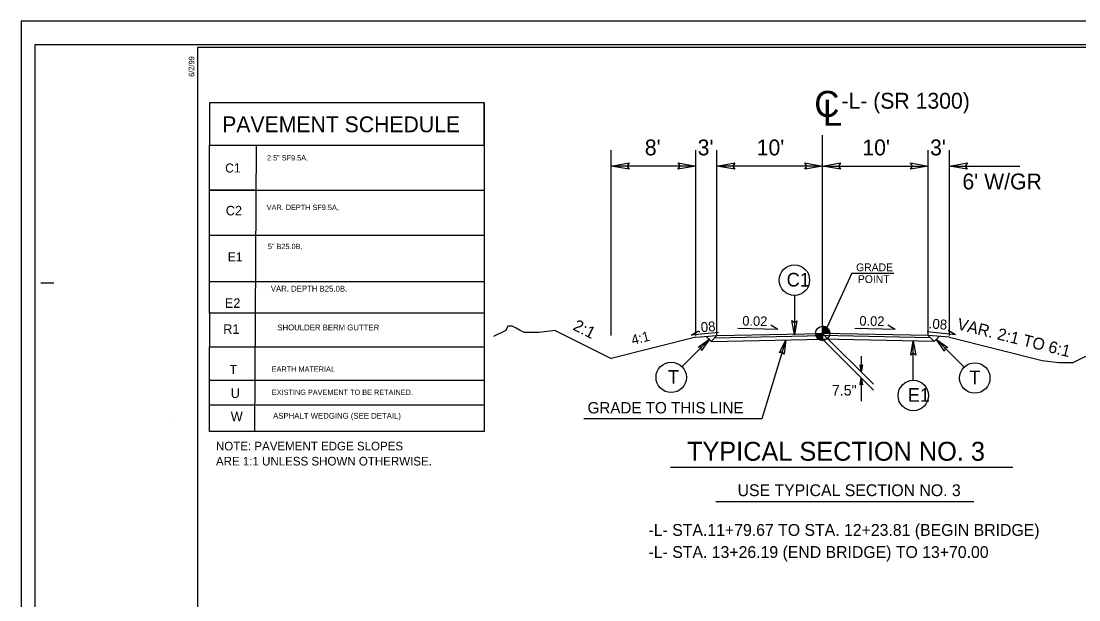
# Model space of a CAD drawing. Extents: x 1818040 to 1825768, y 638918 to 648046.
# Drawn here: x 1820431 to 1821432, y 644582 to 645130 of the extents above; entities that cross this region are included whole.
import ezdxf

# ---------------------------------------------------------------- set-up
doc = ezdxf.new("R2010")
doc.units = 0
for name, color, linetype in [('Old_Level_1', 7, 'Continuous'), ('Prop Dimension', 7, 'Continuous'), ('Prop Dimension Text', 7, 'Continuous'), ('Prop Pavement Schedule Description CELL', 7, 'Continuous'), ('Sheet Plot Border Inside CELL', 7, 'Continuous'), ('Sheet Plot Border Outside CELL', 7, 'Continuous'), ('Sheet Typical CELL', 7, 'Continuous'), ('Typical Grade Point Symbol CELL', 7, 'Continuous'), ('Typical ID Circle CELL', 7, 'Continuous'), ('Typical Pavement Slope CELL', 7, 'Continuous'), ('Typical Pavement Slope Information CELL', 7, 'Continuous'), ('Typical Shoulder Slope CELL', 7, 'Continuous'), ('Typical Slope Point Local CELL', 7, 'Continuous'), ('Typical Terminator CELL', 7, 'Continuous'), ('Typical Text Centerline CELL', 7, 'Continuous'), ('Typical Text General CELL', 7, 'Continuous'), ('Typical Text Grade Point CELL', 7, 'Continuous'), ('Typical Text ID Circle CELL', 7, 'Continuous'), ('Typical Text Label CELL', 7, 'Continuous')]:
    doc.layers.add(name, color=color, linetype=linetype)

msp = doc.modelspace()

# ---------------------------------------------------------------- linework, layer by layer
at = {"layer": 'Old_Level_1'}
for p, q in [((1820989.5, 644832.1), (1820989.5, 645007.5)), ((1821084, 644826.6), (1821079.3, 644831.2)), ((1821089.5, 644832.1), (1821084, 644826.6)), ((1821084, 644826.6), (1821189.5, 644828.7)), ((1821087.4, 644830), (1821189.5, 644832)), ((1821154.6, 644828), (1821131.9, 644753.4)), ((1821189.5, 644834.1), (1821237.5, 644786.1)), ((1821291.7, 644830), (1821189.5, 644832)), ((1821189.5, 644828.7), (1821237.7, 644780.5)), ((1821295.1, 644826.6), (1821189.5, 644828.7)), ((1821289.5, 644832.1), (1821295.1, 644826.6)), ((1821295.1, 644826.6), (1821299.8, 644831.2)), ((1821226, 644812.5), (1821226, 644797.7)), ((1821226, 644792.2), (1821226, 644769.9)), ((1821131.9, 644753.4), (1820963.4, 644753.4))]:
    msp.add_line(p, q, dxfattribs=at)
at = {"layer": 'Prop Dimension'}
for p, q in [((1821189.5, 644834.1), (1821189.5, 645021.8)), ((1821069.5, 644832.1), (1821069.5, 645007.5)), ((1821089.5, 644832.1), (1821089.5, 645007.5)), ((1821289.5, 644832.1), (1821289.5, 645007.5)), ((1821309.5, 644832.1), (1821309.5, 645007.5)), ((1821069.5, 644992.5), (1820989.5, 644992.5)), ((1821189.5, 644992.5), (1821089.5, 644992.5)), ((1821189.5, 644992.5), (1821289.5, 644992.5)), ((1821309.5, 644992.5), (1821376.1, 644992.5))]:
    msp.add_line(p, q, dxfattribs=at)
at = {"layer": 'Prop Pavement Schedule Description CELL'}
for p, q in [((1820869, 645052.4), (1820869, 645012.3)), ((1820653.3, 645012.3), (1820651.7, 644741.2)), ((1820869, 645012.3), (1820869, 644927.1)), ((1820869, 644938.9), (1820869, 644913.4)), ((1820609.3, 644927.1), (1820869, 644927.1)), ((1820609.3, 644883.3), (1820609.3, 644927.1)), ((1820869, 644913.4), (1820869, 644809)), ((1820609.3, 644853.2), (1820609.3, 644821.5)), ((1820869, 644809), (1820869, 644789.7)), ((1820609.3, 644789.7), (1820869, 644789.7)), ((1820869, 644789.7), (1820869, 644741.2)), ((1820574.6, 644754.4), (1820574.6, 644754.4))]:
    msp.add_line(p, q, dxfattribs=at)
msp.add_lwpolyline([(1820609.3, 645012.3), (1820869, 645012.3), (1820869, 645052.4), (1820609.3, 645052.4)], close=True, dxfattribs=at)
for points in [[(1820651.9, 644969.7), (1820609.3, 644969.7), (1820609.3, 645012.3), (1820869, 645012.3)], [(1820609.3, 644927.1), (1820609.3, 644969.7), (1820869, 644969.7)], [(1820869, 644853.2), (1820609.3, 644853.2), (1820609.3, 644883.3), (1820869, 644883.3)], [(1820609.3, 644757.4), (1820609.3, 644821.5), (1820869, 644821.5)], [(1820869, 644741.2), (1820609.3, 644741.2), (1820609.3, 644766.4), (1820869, 644766.4)]]:
    msp.add_lwpolyline(points, dxfattribs=at)
at = {"layer": 'Sheet Plot Border Inside CELL'}
msp.add_lwpolyline([(1822110.4, 645107.2), (1820443.9, 645107.2), (1820443.9, 644052.1), (1822110.4, 644052.1)], close=True, dxfattribs=at)
at = {"layer": 'Sheet Plot Border Outside CELL'}
msp.add_lwpolyline([(1822114.9, 645129.6), (1820430.9, 645129.6), (1820430.9, 644029.6), (1822114.9, 644029.6)], close=True, dxfattribs=at)
at = {"layer": 'Sheet Typical CELL'}
for p, q in [((1822114.9, 645129.6), (1820430.9, 645129.6)), ((1820430.9, 645129.6), (1820430.9, 644029.6)), ((1820449.4, 644882.1), (1820461.9, 644882.1))]:
    msp.add_line(p, q, dxfattribs=at)
msp.add_lwpolyline([(1822097.9, 645104.6), (1820597.9, 645104.6), (1820597.9, 644054.6), (1822097.9, 644054.6)], close=True, dxfattribs=at)
at = {"layer": 'Typical Grade Point Symbol CELL'}
for p, q in [((1821189.5, 644834.1), (1821189.5, 644840.8)), ((1821182.8, 644834.1), (1821189.5, 644834.1)), ((1821196.3, 644834.1), (1821189.5, 644834.1)), ((1821189.5, 644827.4), (1821189.5, 644834.1)), ((1821189.5, 644834.1), (1821189.5, 644827.4))]:
    msp.add_line(p, q, dxfattribs=at)
for points in [[(1821189.6, 644840.8), (1821189.6, 644840.8), (1821189.6, 644834.1)], [(1821189.7, 644840.8), (1821189.7, 644834.1)], [(1821189.9, 644840.8), (1821189.9, 644834.1)], [(1821190, 644840.8), (1821190, 644834.1)], [(1821190.1, 644840.8), (1821190.1, 644834.1)], [(1821190.3, 644840.8), (1821190.3, 644834.1)], [(1821190.4, 644840.8), (1821190.4, 644834.1)], [(1821190.5, 644840.7), (1821190.5, 644834.1)], [(1821190.7, 644840.7), (1821190.7, 644834.1)], [(1821190.8, 644840.7), (1821190.8, 644834.1)], [(1821191, 644840.7), (1821191, 644834.1)], [(1821191.1, 644840.6), (1821191.1, 644834.1)], [(1821191.2, 644840.6), (1821191.2, 644834.1)], [(1821191.4, 644840.6), (1821191.4, 644834.1)], [(1821191.5, 644840.5), (1821191.5, 644834.1)], [(1821191.6, 644840.5), (1821191.6, 644834.1)], [(1821191.8, 644840.4), (1821191.8, 644834.1)], [(1821191.9, 644840.4), (1821191.9, 644834.1)], [(1821192, 644840.3), (1821192, 644834.1)], [(1821192.2, 644840.3), (1821192.2, 644834.1)], [(1821192.3, 644840.2), (1821192.3, 644834.1)], [(1821192.4, 644840.2), (1821192.4, 644834.1)], [(1821192.6, 644840.1), (1821192.6, 644834.1)], [(1821192.7, 644840), (1821192.7, 644834.1)], [(1821192.8, 644839.9), (1821192.8, 644834.1)], [(1821193, 644839.9), (1821193, 644834.1)], [(1821193.1, 644839.8), (1821193.1, 644834.1)], [(1821193.2, 644839.7), (1821193.2, 644834.1)], [(1821193.4, 644839.6), (1821193.4, 644834.1)], [(1821193.5, 644839.5), (1821193.5, 644834.1)], [(1821193.6, 644839.4), (1821193.6, 644834.1)], [(1821193.8, 644839.3), (1821193.8, 644834.1)], [(1821193.9, 644839.2), (1821193.9, 644834.1)], [(1821194, 644839.1), (1821194, 644834.1)], [(1821194.2, 644839), (1821194.2, 644834.1)], [(1821194.3, 644838.8), (1821194.3, 644834.1)], [(1821194.4, 644838.7), (1821194.4, 644834.1)], [(1821194.6, 644838.5), (1821194.6, 644834.1)], [(1821194.7, 644838.4), (1821194.7, 644834.1)], [(1821194.8, 644838.2), (1821194.8, 644834.1)], [(1821195, 644838), (1821195, 644834.1)], [(1821195.1, 644837.8), (1821195.1, 644834.1)], [(1821195.2, 644837.6), (1821195.2, 644834.1)], [(1821195.4, 644837.4), (1821195.4, 644834.1)], [(1821195.5, 644837.2), (1821195.5, 644834.1)], [(1821195.6, 644836.9), (1821195.6, 644834.1)], [(1821195.8, 644836.6), (1821195.8, 644834.1)], [(1821195.9, 644836.2), (1821195.9, 644834.1)], [(1821196.1, 644835.7), (1821196.1, 644834.1)], [(1821182.9, 644834.1), (1821182.9, 644833.4)], [(1821183, 644834.1), (1821183, 644832.6)], [(1821183.1, 644834.1), (1821183.1, 644832.1)], [(1821183.3, 644834.1), (1821183.3, 644831.7)], [(1821183.4, 644834.1), (1821183.4, 644831.4)], [(1821183.5, 644834.1), (1821183.5, 644831.1)], [(1821183.7, 644834.1), (1821183.7, 644830.8)], [(1821183.8, 644834.1), (1821183.8, 644830.6)], [(1821183.9, 644834.1), (1821183.9, 644830.4)], [(1821184.1, 644834.1), (1821184.1, 644830.2)], [(1821184.2, 644834.1), (1821184.2, 644830)], [(1821184.3, 644834.1), (1821184.3, 644829.9)], [(1821184.5, 644834.1), (1821184.5, 644829.7)], [(1821184.6, 644834.1), (1821184.6, 644829.5)], [(1821184.7, 644834.1), (1821184.7, 644829.4)], [(1821184.9, 644834.1), (1821184.9, 644829.3)], [(1821185, 644834.1), (1821185, 644829.1)], [(1821185.1, 644834.1), (1821185.1, 644829)], [(1821185.3, 644834.1), (1821185.3, 644828.9)], [(1821185.4, 644834.1), (1821185.4, 644828.8)], [(1821185.5, 644834.1), (1821185.5, 644828.7)], [(1821185.7, 644834.1), (1821185.7, 644828.6)], [(1821185.8, 644834.1), (1821185.8, 644828.5)], [(1821186, 644834.1), (1821186, 644828.4)], [(1821186.1, 644834.1), (1821186.1, 644828.3)], [(1821186.2, 644834.1), (1821186.2, 644828.3)], [(1821186.4, 644834.1), (1821186.4, 644828.2)], [(1821186.5, 644834.1), (1821186.5, 644828.1)], [(1821186.6, 644834.1), (1821186.6, 644828.1)], [(1821186.8, 644834.1), (1821186.8, 644828)], [(1821186.9, 644834.1), (1821186.9, 644827.9)], [(1821187, 644834.1), (1821187, 644827.9)], [(1821187.2, 644834.1), (1821187.2, 644827.8)], [(1821187.3, 644834.1), (1821187.3, 644827.8)], [(1821187.4, 644834.1), (1821187.4, 644827.7)], [(1821187.6, 644834.1), (1821187.6, 644827.7)], [(1821187.7, 644834.1), (1821187.7, 644827.7)], [(1821187.8, 644834.1), (1821187.8, 644827.6)], [(1821188, 644834.1), (1821188, 644827.6)], [(1821188.1, 644834.1), (1821188.1, 644827.5)], [(1821188.2, 644834.1), (1821188.2, 644827.5)], [(1821188.4, 644834.1), (1821188.4, 644827.5)], [(1821188.5, 644834.1), (1821188.5, 644827.5)], [(1821188.6, 644834.1), (1821188.6, 644827.4)], [(1821188.8, 644834.1), (1821188.8, 644827.4)], [(1821188.9, 644834.1), (1821188.9, 644827.4)], [(1821189, 644834.1), (1821189, 644827.4)], [(1821189.2, 644834.1), (1821189.2, 644827.4)], [(1821189.3, 644834.1), (1821189.3, 644827.4)], [(1821189.4, 644834.1), (1821189.4, 644827.4), (1821189.4, 644827.4)], [(1821196.2, 644835.1), (1821196.2, 644834.1)]]:
    msp.add_lwpolyline(points, dxfattribs=at)
msp.add_circle((1821189.5, 644834.1), 6.71, dxfattribs=at)
for start, end in [(359.9905, 89.9905), (179.9905, 269.9905)]:
    msp.add_arc((1821189.5, 644834.1), 6.71, start, end, dxfattribs=at)
at = {"layer": 'Typical ID Circle CELL'}
for p, q in [((1821162.8, 644870.1), (1821162.8, 644832.8)), ((1821056.4, 644802.7), (1821082.8, 644829)), ((1821275.3, 644789.7), (1821275.3, 644827)), ((1821323.3, 644802.1), (1821297, 644828.5))]:
    msp.add_line(p, q, dxfattribs=at)
for centre in [(1821162.8, 644884.5), (1821046.2, 644792.5), (1821333.5, 644791.9), (1821275.3, 644775.3), (1821275.3, 644775.3)]:
    msp.add_circle(centre, 14.4, dxfattribs=at)
at = {"layer": 'Typical Pavement Slope CELL'}
for p in [(1821089.5, 644832.1), (1821289.5, 644832.1)]:
    msp.add_line(p, (1821189.5, 644834.1), dxfattribs=at)
at = {"layer": 'Typical Pavement Slope Information CELL'}
for p, q in [((1821065.2, 644832.4), (1821072.1, 644836.6)), ((1821147.2, 644837.8), (1821109.3, 644838.6)), ((1821147.2, 644837.8), (1821140.5, 644841.9)), ((1821258, 644837.8), (1821220, 644838.6)), ((1821258, 644837.8), (1821251.2, 644841.9)), ((1821315.2, 644832.9), (1821288.3, 644835.5)), ((1821315.2, 644832.9), (1821308.3, 644837)), ((1821091, 644834.9), (1821065.2, 644832.4))]:
    msp.add_line(p, q, dxfattribs=at)
at = {"layer": 'Typical Shoulder Slope CELL'}
for p, q in [((1821069.5, 644830.4), (1821089.5, 644832.1)), ((1821309.5, 644830.4), (1821289.5, 644832.1))]:
    msp.add_line(p, q, dxfattribs=at)
at = {"layer": 'Typical Slope Point Local CELL'}
for p, q in [((1820936.3, 644837), (1820989.5, 644810.4)), ((1821069.5, 644830.4), (1820989.5, 644810.4)), ((1821309.5, 644830.4), (1821397.3, 644808.5))]:
    msp.add_line(p, q, dxfattribs=at)
for points in [[(1820936.3, 644837), (1820920.8, 644835.1), (1820916.9, 644835.1), (1820911.1, 644835.1), (1820907.2, 644835.1), (1820903.3, 644837), (1820899.4, 644839), (1820895.5, 644840.9), (1820891.6, 644840.9), (1820889.7, 644837), (1820885.8, 644835.1), (1820881.9, 644833.1), (1820878, 644831.2)], [(1821397.3, 644808.5), (1821412.9, 644806.6), (1821416.7, 644806.6), (1821422.6, 644806.6), (1821426.5, 644806.6), (1821430.4, 644808.5), (1821434.3, 644810.4), (1821438.1, 644812.4), (1821442, 644812.4), (1821444, 644808.5), (1821447.9, 644806.6), (1821451.8, 644804.6), (1821455.7, 644802.7), (1821459.6, 644802.7), (1821463.4, 644802.7), (1821467.3, 644802.7), (1821471.2, 644802.7), (1821475.1, 644802.7)]]:
    msp.add_lwpolyline(points, dxfattribs=at)
at = {"layer": 'Typical Terminator CELL'}
for points in [[(1821006.4, 644989.6), (1820989.5, 644992.5), (1821006.5, 644995.5), (1821004.4, 644992.5)], [(1821052.7, 644995.5), (1821069.5, 644992.5), (1821052.6, 644989.5), (1821054.7, 644992.5)], [(1821106.4, 644989.6), (1821089.5, 644992.5), (1821106.5, 644995.5), (1821104.4, 644992.5)], [(1821172.7, 644995.5), (1821189.5, 644992.5), (1821172.6, 644989.5), (1821174.7, 644992.5)], [(1821206.4, 644989.6), (1821189.5, 644992.5), (1821206.5, 644995.5), (1821204.4, 644992.5)], [(1821272.7, 644995.5), (1821289.5, 644992.5), (1821272.6, 644989.5), (1821274.7, 644992.5)], [(1821326.4, 644989.6), (1821309.5, 644992.5), (1821326.5, 644995.5), (1821324.4, 644992.5)], [(1821165.1, 644846.1), (1821162.8, 644832.8), (1821160.4, 644846.2), (1821162.8, 644844.5)], [(1821071.7, 644821.2), (1821082.8, 644829), (1821074.9, 644817.9), (1821074.5, 644820.8)], [(1821148.6, 644815.8), (1821154.7, 644828), (1821153.1, 644814.4), (1821151.3, 644816.7)], [(1821273, 644813.6), (1821275.3, 644827), (1821277.7, 644813.6), (1821275.3, 644815.3)], [(1821304.8, 644817.4), (1821297, 644828.5), (1821308.1, 644820.7), (1821305.3, 644820.2)], [(1821227.2, 644804.4), (1821226, 644797.7), (1821224.9, 644804.4), (1821226.1, 644803.6)], [(1821224.9, 644785.5), (1821226, 644792.2), (1821227.2, 644785.5), (1821226.1, 644786.3)]]:
    msp.add_lwpolyline(points, close=True, dxfattribs=at)
at = {"layer": 'Typical Text Grade Point CELL'}
for q in [(1821191.1, 644834.1), (1821256.9, 644891.2)]:
    msp.add_line((1821217.1, 644891.2), q, dxfattribs=at)
at = {"layer": 'Typical Text Label CELL'}
for p, q in [((1821045.5, 644707.6), (1821369.5, 644707.6)), ((1821088.3, 644675), (1821332.7, 644675))]:
    msp.add_line(p, q, dxfattribs=at)

# ---------------------------------------------------------------- texts
at = {"layer": 'Prop Dimension Text'}
for s, height, p in [('-L- (SR 1300)', 15, (1821207.3, 645046.8)), ("8'", 15, (1821021.2, 645002.6)), ("3'", 15, (1821071.2, 645002.6)), ("10'", 15, (1821127.1, 645002.6)), ("10'", 15, (1821227.1, 645002.6)), ("3'", 15, (1821291.2, 645002.6)), ("6' W/GR", 15, (1821321.8, 644970.4)), ('7.5"', 10, (1821198.3, 644775.3))]:
    msp.add_text(s, height=height, dxfattribs=at).set_placement(p)
at = {"layer": 'Prop Pavement Schedule Description CELL'}
for s, height, p in [('PAVEMENT SCHEDULE', 15, (1820621.2, 645024.5)), (' 2.5" SF9.5A, ', 5, (1820661.7, 644997.8)), ('C1', 8.51, (1820624, 644986.4)), (' VAR. DEPTH SF9.5A, ', 5, (1820661.4, 644950.9)), ('C2', 8.98, (1820624.6, 644945.8)), (' 5" B25.0B, ', 5, (1820662.5, 644913.9)), ('E1', 8.51, (1820626.5, 644902.3)), ('VAR. DEPTH B25.0B.', 5.5, (1820667.2, 644873.7)), ('E2', 8.98, (1820623.7, 644858.3)), ('R1', 8.98, (1820622.2, 644833.7)), ('SHOULDER BERM GUTTER', 5.5, (1820673.4, 644837)), ('T', 8.51, (1820628.3, 644795.6)), ('EARTH MATERIAL ', 5, (1820668.1, 644797.8)), ('U', 8.98, (1820629.3, 644773)), ('EXISTING PAVEMENT TO BE RETAINED.', 5, (1820668.2, 644775.9)), ('W', 8.98, (1820629.3, 644751)), ('ASPHALT WEDGING (SEE DETAIL)', 5.5, (1820669.4, 644753.4)), ('NOTE: PAVEMENT EDGE SLOPES ', 8.162, (1820615.3, 644723.4)), ('ARE 1:1 UNLESS SHOWN OTHERWISE.', 8.162, (1820615.3, 644709.1))]:
    msp.add_text(s, height=height, dxfattribs=at).set_placement(p)
at = {"layer": 'Sheet Typical CELL'}
msp.add_text('6/2/99', height=5.25, rotation=90, dxfattribs=at).set_placement((1820594.8, 645076.9))
at = {"layer": 'Typical Pavement Slope Information CELL'}
for p in [(1821113.4, 644841.5), (1821224.2, 644841.5)]:
    msp.add_text('0.02 ', height=9.11, rotation=358.8543, dxfattribs=at).set_placement(p)
at = {"layer": 'Typical Slope Point Local CELL'}
for s, rotation, p in [('.08', 4.7615, (1821071.1, 644834.9)), ('.08', 355.2385, (1821289.6, 644839)), ('4:1', 14.0362, (1821009.7, 644823.1))]:
    msp.add_text(s, height=9.37, rotation=rotation, dxfattribs=at).set_placement(p)
at = {"layer": 'Typical Text Centerline CELL'}
msp.add_text('C', height=24.6, dxfattribs=at).set_placement((1821181.6, 645039))
msp.add_text('L', height=24.6, rotation=359.9469, dxfattribs=at).set_placement((1821189.8, 645030.6))
at = {"layer": 'Typical Text General CELL'}
for s, rotation, p in [('2:1 ', 333.4349, (1820952.3, 644837.9)), ('VAR. 2:1 TO 6:1', 345.9638, (1821316, 644838.1))]:
    msp.add_text(s, height=11.19, rotation=rotation, dxfattribs=at).set_placement(p)
msp.add_text('GRADE TO THIS LINE', height=10.742, dxfattribs=at).set_placement((1820967, 644758.4))
at = {"layer": 'Typical Text Grade Point CELL'}
for s, height, p in [('GRADE', 7.34, (1821221.2, 644893)), ('POINT', 7.34, (1821222.9, 644881.8)), ('-L- STA.11+79.67 TO STA. 12+23.81 (BEGIN BRIDGE)', 11.19, (1821024.7, 644642.5)), ('-L- STA. 13+26.19 (END BRIDGE) TO 13+70.00 ', 11.19, (1821024.7, 644621.6))]:
    msp.add_text(s, height=height, dxfattribs=at).set_placement(p)
at = {"layer": 'Typical Text ID Circle CELL'}
for s, height, p in [('C1', 12.91, (1821155.4, 644878.5)), ('T', 12.9, (1821043, 644786.5)), ('T', 12.9, (1821328.2, 644786)), ('E1', 12.91, (1821270, 644769.4))]:
    msp.add_text(s, height=height, dxfattribs=at).set_placement(p)
at = {"layer": 'Typical Text Label CELL'}
for s, height, p in [('TYPICAL SECTION NO. 3  ', 17.903, (1821061.1, 644713.6)), ('USE TYPICAL SECTION NO. 3', 11.19, (1821109, 644680.1))]:
    msp.add_text(s, height=height, dxfattribs=at).set_placement(p)

doc.saveas('drawing.dxf')
